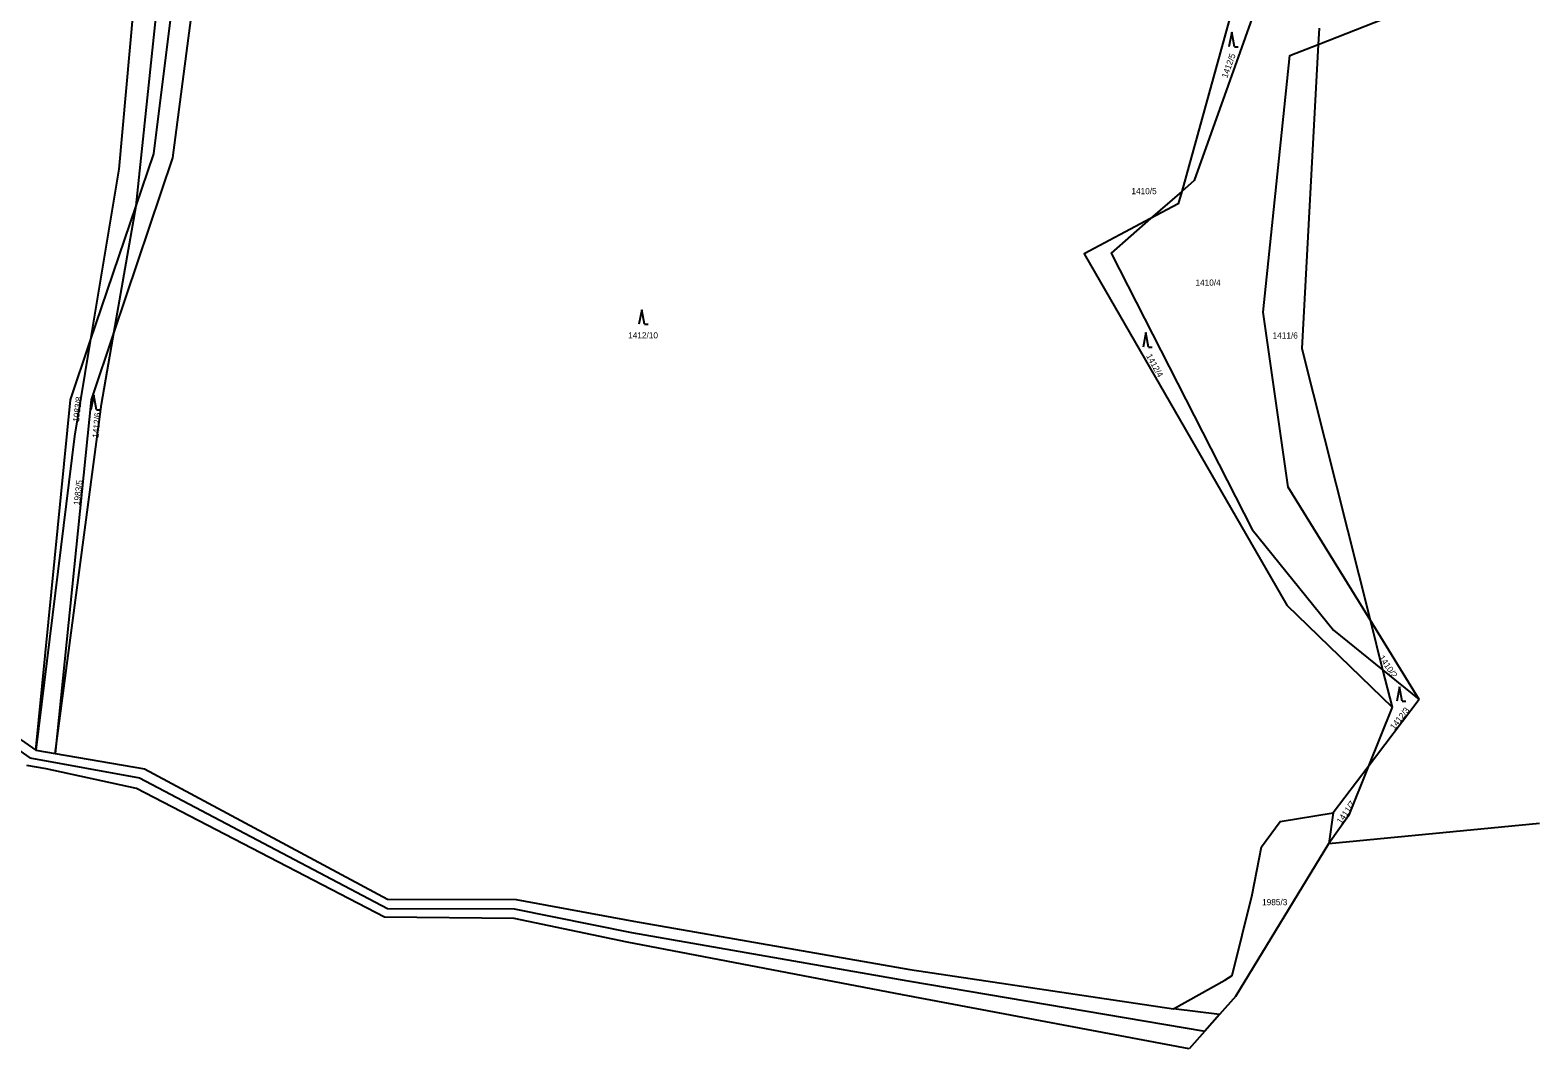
# Model space of a CAD drawing. Extents: x -793666 to -785424, y -1118958 to -1108761.
# Drawn here: x -786143.7 to -785728.5, y -1118840.3 to -1118559.9 of the extents above; entities that cross this region are included whole.
import ezdxf

# ---------------------------------------------------------------- set-up
doc = ezdxf.new("R2010")
doc.units = 0
for name, color, linetype in [('Hranice parcel', 7, 'Continuous'), ('Parcelní čísla', 7, 'Continuous'), ('Značky kultur', 7, 'Continuous')]:
    doc.layers.add(name, color=color, linetype=linetype)

msp = doc.modelspace()

# ---------------------------------------------------------------- linework, layer by layer
at = {"layer": 'Hranice parcel'}
for p, q in [((-786114.45, -1118608.23), (-786097.17, -1118443.33)), ((-785809.94, -1118544.3), (-785826.56, -1118604.28)), ((-785788.98, -1118563.83), (-785752.48, -1118549.46)), ((-785788.74, -1118559.33), (-785788.98, -1118563.83)), ((-785826.56, -1118604.28), (-785835.11, -1118611.77)), ((-786127.09, -1118645.52), (-786114.45, -1118608.23)), ((-786120.51, -1118642.74), (-786114.45, -1118608.23)), ((-785761.15, -1118744.17), (-785774.68, -1118722.25)), ((-785774.68, -1118722.25), (-785771.23, -1118735.99)), ((-785771.23, -1118735.99), (-785761.15, -1118744.17)), ((-785771.23, -1118735.99), (-785768.64, -1118746.29)), ((-785761.15, -1118744.17), (-785775.19, -1118762.7)), ((-785768.64, -1118746.29), (-785775.19, -1118762.7)), ((-786142.08, -1118758.1), (-786136.76, -1118759.03)), ((-786139.26, -1118763.27), (-786144.62, -1118762.37)), ((-785775.19, -1118762.7), (-785784.81, -1118775.39)), ((-785784.81, -1118775.39), (-785786.04, -1118783.81)), ((-785786.04, -1118783.81), (-785728.07, -1118778.18)), ((-785811.67, -1118825.83), (-785786.04, -1118783.81)), ((-785811.67, -1118825.83), (-785816.17, -1118830.91)), ((-785816.17, -1118830.91), (-785828.82, -1118829.31)), ((-785816.17, -1118830.91), (-785820.18, -1118835.44)), ((-785820.18, -1118835.44), (-785824.49, -1118840.32))]:
    msp.add_line(p, q, dxfattribs=at)
for points in [[(-786048.89, -1118427.82), (-786072.67, -1118471.58), (-786097.69, -1118543.13), (-786104.44, -1118595.02), (-786120.51, -1118642.74)], [(-786114.45, -1118608.23), (-786109.6, -1118593.93), (-786103.17, -1118542.43), (-786079.19, -1118471.01), (-786076.97, -1118462.09), (-786059.03, -1118433.1)], [(-786105.36, -1118444.39), (-786119.23, -1118598.18), (-786127.09, -1118645.52)], [(-785804.39, -1118548.75), (-785823.15, -1118601.29), (-785826.56, -1118604.28)], [(-785774.68, -1118722.25), (-785797.21, -1118685.75), (-785804.16, -1118637.51), (-785796.76, -1118566.89), (-785788.98, -1118563.83)], [(-785788.98, -1118563.83), (-785793.46, -1118647.53), (-785774.68, -1118722.25)], [(-785826.56, -1118604.28), (-785827.52, -1118607.75), (-785835.11, -1118611.77)], [(-786510.78, -1118609.35), (-786478.08, -1118622.08), (-786419.11, -1118635.51), (-786367.48, -1118640.28), (-786331.99, -1118647.56), (-786281.51, -1118671.77), (-786222.51, -1118692.62), (-786191.1, -1118724.1), (-786142.08, -1118758.1)], [(-786846.94, -1118704.41), (-786827.58, -1118701.84), (-786782.57, -1118700.19), (-786751.5, -1118702.99), (-786731.15, -1118699.93), (-786650.96, -1118661.54), (-786598.77, -1118638.01), (-786547.14, -1118616.54), (-786524.64, -1118611.45), (-786510.81, -1118611.35), (-786478.81, -1118623.94), (-786419.49, -1118637.18), (-786367.82, -1118641.96), (-786332.76, -1118649.17), (-786282.28, -1118673.38), (-786224.24, -1118694.35), (-786192.5, -1118726.11), (-786143.78, -1118760.19), (-786113.53, -1118765.76), (-786045.22, -1118801.66), (-786010.35, -1118801.79), (-785978.1, -1118808.31), (-785902.01, -1118821.63), (-785820.18, -1118835.44)], [(-785835.11, -1118611.77), (-785853.39, -1118621.45), (-785797.58, -1118718.18), (-785768.64, -1118746.29)], [(-785835.11, -1118611.77), (-785846.02, -1118621.33), (-785807.13, -1118697.37), (-785784.72, -1118725.03), (-785771.23, -1118735.99)], [(-786136.76, -1118759.03), (-786124.04, -1118662.89), (-786120.51, -1118642.74)], [(-786120.51, -1118642.74), (-786126.88, -1118661.68), (-786136.76, -1118759.03)], [(-786127.09, -1118645.52), (-786131.43, -1118671.69), (-786142.08, -1118758.1)], [(-786142.08, -1118758.1), (-786132.56, -1118661.67), (-786127.09, -1118645.52)], [(-786136.76, -1118759.03), (-786112.16, -1118763.2), (-786045.22, -1118799.16), (-786009.87, -1118799.2), (-785977.55, -1118805.15), (-785901.46, -1118818.47), (-785828.82, -1118829.31)], [(-785824.49, -1118840.32), (-785903.44, -1118825.43), (-785979.24, -1118810.99), (-786010.37, -1118804.44), (-786046.11, -1118804.04), (-786114.41, -1118768.64), (-786139.26, -1118763.27)], [(-785775.19, -1118762.7), (-785780.59, -1118776.22), (-785786.04, -1118783.81)], [(-785828.82, -1118829.31), (-785814.64, -1118821.46), (-785812.68, -1118820.13), (-785807.15, -1118797.91), (-785804.55, -1118784.7), (-785799.43, -1118777.71), (-785784.81, -1118775.39)]]:
    msp.add_lwpolyline(points, dxfattribs=at)
at = {"layer": 'Značky kultur'}
for p, q in [((-785812.79, -1118560.5), (-785813.54, -1118564.5)), ((-785812.04, -1118564.5), (-785812.79, -1118560.5)), ((-785812.04, -1118564.5), (-785811.04, -1118564.5)), ((-785975.26, -1118636.87), (-785976.01, -1118640.87)), ((-785974.51, -1118640.87), (-785975.26, -1118636.87)), ((-785974.51, -1118640.87), (-785973.51, -1118640.87)), ((-785836.46, -1118643.14), (-785837.21, -1118647.14)), ((-785835.71, -1118647.14), (-785836.46, -1118643.14)), ((-785835.71, -1118647.14), (-785834.71, -1118647.14)), ((-786126.16, -1118660.42), (-786126.91, -1118664.42)), ((-786125.41, -1118664.42), (-786126.16, -1118660.42)), ((-786125.41, -1118664.42), (-786124.41, -1118664.42)), ((-785766.59, -1118740.65), (-785767.34, -1118744.65)), ((-785765.84, -1118744.65), (-785766.59, -1118740.65)), ((-785765.84, -1118744.65), (-785764.84, -1118744.65))]:
    msp.add_line(p, q, dxfattribs=at)

# ---------------------------------------------------------------- texts
at = {"layer": 'Parcelní čísla'}
for s, rotation, p in [('1412/5', 70, (-785814.04, -1118573.25)), ('1412/4', 299, (-785836.4, -1118649.59)), ('1983/8', 83, (-786130.22, -1118667.83)), ('1412/6', 85, (-786124.83, -1118672.2)), ('1983/5', 83, (-786130.04, -1118690.77)), ('1410/2', 305, (-785772.37, -1118732.71)), ('1412/3', 52, (-785767.99, -1118752.63)), ('1411/7', 56, (-785782.58, -1118778.58))]:
    msp.add_text(s, height=1.7, rotation=rotation, dxfattribs=at).set_placement(p)
for s, p in [('1410/5', (-785840.4, -1118605.06)), ('1410/4', (-785822.76, -1118630.25)), ('1412/10', (-785978.99, -1118644.77)), ('1411/6', (-785801.52, -1118644.8)), ('1985/3', (-785804.42, -1118800.79))]:
    msp.add_text(s, height=1.7, dxfattribs=at).set_placement(p)

doc.saveas('drawing.dxf')
